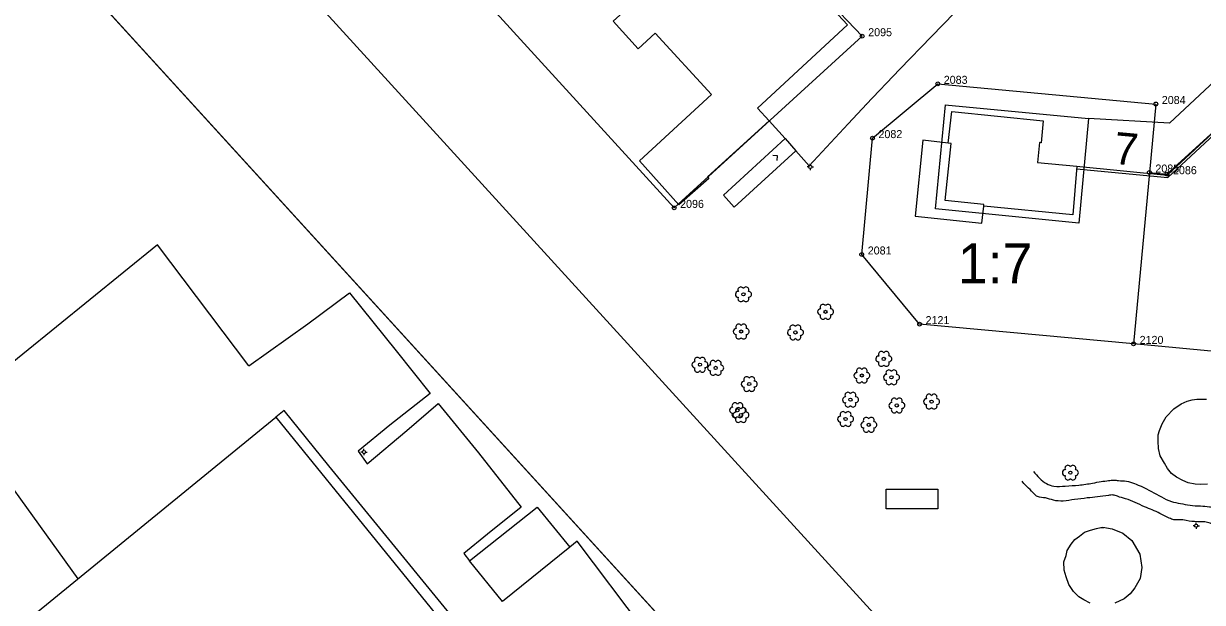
# Model space of a CAD drawing. Extents: x 1517693 to 1518189, y 6494860 to 6495280.
# Drawn here: x 1517936.6 to 1518083.9, y 6495063.4 to 6495135.7 of the extents above; entities that cross this region are included whole.
import ezdxf

# ---------------------------------------------------------------- set-up
doc = ezdxf.new("R2010")
doc.units = 0
for name, color, linetype in [('adress', 7, 'Continuous'), ('allmanbyggnad', 7, 'Continuous'), ('altan', 7, 'Continuous'), ('bostadshus', 7, 'Continuous'), ('fastighetsbeteckning', 7, 'Continuous'), ('gc_vag', 7, 'Continuous'), ('grans', 7, 'Continuous'), ('granspunkt', 7, 'Continuous'), ('granspunkt_text', 7, 'Continuous'), ('kvartersgrans', 7, 'Continuous'), ('kvartersgrans_utan_fastgr', 7, 'Continuous'), ('lovtrad', 7, 'Continuous'), ('parkeringskant', 7, 'Continuous'), ('planteringskant', 7, 'Continuous'), ('skarmtak', 7, 'Continuous'), ('staket', 7, 'Continuous'), ('stenmur', 7, 'Continuous'), ('stolpe_belysning', 7, 'Continuous'), ('trappa', 7, 'Continuous'), ('trappsymbol', 7, 'Continuous'), ('uthus', 7, 'Continuous')]:
    doc.layers.add(name, color=color, linetype=linetype)

msp = doc.modelspace()

# ---------------------------------------------------------------- linework, layer by layer
at = {"layer": 'allmanbyggnad'}
msp.add_lwpolyline([(1517931.88, 6495057.02), (1517968.08, 6495086.54), (1517994.34, 6495054.25)], dxfattribs=at)
at = {"layer": 'altan'}
msp.add_lwpolyline([(1518052.12, 6495120.78), (1518048.93, 6495121.18), (1518048, 6495111.68), (1518056.33, 6495110.79), (1518056.56, 6495112.9)], dxfattribs=at)
at = {"layer": 'bostadshus'}
for points in [[(1518010.24, 6495136.01), (1518021.49, 6495146.21), (1518024.66, 6495142.89), (1518028.99, 6495146.91), (1518039.53, 6495135.57), (1518028.29, 6495125.18), (1518029.76, 6495123.58), (1518022.02, 6495116.58), (1518022.18, 6495116.39), (1518018.47, 6495113.08), (1518013.52, 6495118.58), (1518022.53, 6495126.88), (1518015.48, 6495134.51), (1518013.35, 6495132.59), (1518010.23, 6495136.01)], [(1518052.55, 6495124.74), (1518064, 6495123.59), (1518063.75, 6495120.85), (1518063.52, 6495120.86), (1518063.29, 6495118.38), (1518068.2, 6495117.91), (1518067.7, 6495111.84), (1518056.56, 6495112.9), (1518056.56, 6495113.13), (1518051.72, 6495113.61), (1518052.47, 6495120.74), (1518052.12, 6495120.78), (1518052.55, 6495124.74)]]:
    msp.add_lwpolyline(points, dxfattribs=at)
at = {"layer": 'gc_vag'}
for points in [[(1518097.3, 6495139.7), (1518079.77, 6495123.29), (1518069.67, 6495123.88)], [(1518041.89, 6495125.55), (1518041.87, 6495125.6), (1518046.09, 6495130.04), (1518050.01, 6495134.11), (1518054.38, 6495138.58)], [(1518033.07, 6495119.83), (1518034.72, 6495117.97), (1518039.6, 6495123.22), (1518041.95, 6495125.7)]]:
    msp.add_lwpolyline(points, dxfattribs=at)
for points in [[(1518062.77, 6495079.75), (1518063.52, 6495078.94), (1518064.39, 6495078.26), (1518065.32, 6495077.95), (1518066.75, 6495077.95), (1518068.43, 6495078.07), (1518070.17, 6495078.32), (1518071.23, 6495078.51), (1518072.16, 6495078.63), (1518072.78, 6495078.69), (1518073.4, 6495078.63), (1518074.4, 6495078.57), (1518075.39, 6495078.26), (1518076.32, 6495077.89)], [(1518088.99, 6495072.13), (1518086.72, 6495072.79), (1518085.2, 6495073.19), (1518084.51, 6495073.41), (1518083.27, 6495073.5), (1518081.87, 6495073.63), (1518080.97, 6495073.75), (1518080.47, 6495073.72), (1518079.88, 6495073.88), (1518078.58, 6495074.53), (1518076.65, 6495075.37), (1518074.29, 6495076.36), (1518073.26, 6495076.67), (1518072.74, 6495076.83), (1518072.14, 6495076.77), (1518070.78, 6495076.61), (1518069.5, 6495076.46), (1518067.92, 6495076.27), (1518066.49, 6495076.08), (1518065.28, 6495076.18), (1518064.28, 6495076.46), (1518063.29, 6495076.64), (1518062.85, 6495076.98), (1518062.17, 6495077.67), (1518061.8, 6495078.01), (1518061.36, 6495078.57)], [(1518076.25, 6495077.92), (1518078.76, 6495076.61), (1518080.01, 6495076.02), (1518081.13, 6495075.77), (1518082.34, 6495075.55), (1518083.64, 6495075.46), (1518084.76, 6495075.37), (1518085.35, 6495075.28), (1518086.1, 6495075.03), (1518087.96, 6495074.44), (1518089.3, 6495074.06)]]:
    msp.add_spline(points, degree=3, dxfattribs=at)
at = {"layer": 'grans'}
for p, q in [((1518041.37, 6495134.15), (1518015.43, 6495161.24)), ((1517942.78, 6495142.01), (1518054.69, 6495019.3)), ((1517992.59, 6495140.41), (1518017.86, 6495112.7)), ((1518017.86, 6495112.7), (1518041.37, 6495134.15)), ((1518079.46, 6495116.91), (1518095.04, 6495131.13)), ((1518042.65, 6495121.42), (1518050.81, 6495128.2)), ((1518050.81, 6495128.2), (1518078.06, 6495125.68)), ((1518078.06, 6495125.68), (1518077.26, 6495117.12)), ((1518041.31, 6495106.88), (1518042.65, 6495121.42)), ((1518077.26, 6495117.12), (1518075.29, 6495095.71)), ((1518077.26, 6495117.12), (1518079.46, 6495116.91)), ((1518048.54, 6495098.18), (1518041.31, 6495106.88)), ((1518075.29, 6495095.71), (1518048.54, 6495098.18)), ((1518097.62, 6495093.65), (1518075.29, 6495095.71))]:
    msp.add_line(p, q, dxfattribs=at)
at = {"layer": 'granspunkt'}
for centre in [(1518041.37, 6495134.15), (1518050.81, 6495128.2), (1518078.06, 6495125.68), (1518042.65, 6495121.42), (1518077.26, 6495117.12), (1518079.46, 6495116.91), (1518017.86, 6495112.7), (1518041.31, 6495106.88), (1518048.54, 6495098.18), (1518075.29, 6495095.71)]:
    msp.add_circle(centre, 0.237, dxfattribs=at)
at = {"layer": 'kvartersgrans'}
msp.add_lwpolyline([(1517905.68, 6495182.68), (1517942.78, 6495142.01), (1518054.69, 6495019.3)], dxfattribs=at)
at = {"layer": 'kvartersgrans_utan_fastgr'}
msp.add_line((1517921.04, 6495195.52), (1518074.11, 6495027.69), dxfattribs=at)
at = {"layer": 'lovtrad'}
for centre in [(1518026.52, 6495101.91), (1518036.78, 6495099.72), (1518026.24, 6495097.26), (1518033.02, 6495097.14), (1518044.06, 6495093.84), (1518021.09, 6495093.11), (1518023.05, 6495092.71), (1518041.32, 6495091.76), (1518045.02, 6495091.54), (1518027.25, 6495090.7), (1518039.9, 6495088.74), (1518045.69, 6495088.02), (1518050.04, 6495088.5), (1518025.78, 6495087.42), (1518026.2, 6495086.82), (1518039.29, 6495086.33), (1518042.19, 6495085.6), (1518067.38, 6495079.63)]:
    msp.add_circle(centre, 0.2, dxfattribs=at)
for centre, start, end in [((1518026.2, 6495102.46), 29.1347, 212.3057), ((1518026.84, 6495102.46), 329.1331, 150.8613), ((1518025.89, 6495101.9), 89.5389, 268.9887), ((1518026.2, 6495101.36), 150.5831, 330.865), ((1518026.84, 6495101.36), 209.1844, 30.8583), ((1518027.16, 6495101.91), 269.1508, 90.8733), ((1518036.15, 6495099.72), 89.5389, 268.9887), ((1518036.46, 6495100.28), 29.1347, 212.3057), ((1518037.1, 6495100.28), 329.1331, 150.8613), ((1518037.42, 6495099.72), 269.1508, 90.8733), ((1518036.46, 6495099.17), 150.5831, 330.865), ((1518037.1, 6495099.17), 209.1844, 30.8583), ((1518025.61, 6495097.25), 89.5389, 268.9887), ((1518025.92, 6495097.81), 29.1347, 212.3057), ((1518025.92, 6495096.7), 150.5831, 330.865), ((1518026.56, 6495097.81), 329.1331, 150.8613), ((1518026.56, 6495096.7), 209.1844, 30.8583), ((1518026.88, 6495097.26), 269.1508, 90.8733), ((1518032.39, 6495097.14), 89.5389, 268.9887), ((1518032.7, 6495097.7), 29.1347, 212.3057), ((1518033.34, 6495097.7), 329.1331, 150.8613), ((1518033.66, 6495097.14), 269.1508, 90.8733), ((1518032.7, 6495096.59), 150.5831, 330.865), ((1518033.34, 6495096.59), 209.1844, 30.8583), ((1518020.77, 6495093.66), 29.1347, 212.3057), ((1518021.4, 6495093.66), 329.1331, 150.8613), ((1518043.43, 6495093.83), 89.5389, 268.9887), ((1518043.75, 6495094.39), 29.1347, 212.3057), ((1518044.38, 6495094.39), 329.1331, 150.8613), ((1518044.7, 6495093.84), 269.1508, 90.8733), ((1518020.45, 6495093.1), 89.5389, 268.9887), ((1518020.77, 6495092.55), 150.5831, 330.865), ((1518021.4, 6495092.55), 209.1844, 30.8583), ((1518021.72, 6495093.11), 269.1508, 90.8733), ((1518022.42, 6495092.71), 89.5389, 268.9887), ((1518022.73, 6495093.27), 29.1347, 212.3057), ((1518023.37, 6495093.27), 329.1331, 150.8613), ((1518023.69, 6495092.71), 269.1508, 90.8733), ((1518041, 6495092.31), 29.1347, 212.3057), ((1518041.64, 6495092.31), 329.1331, 150.8613), ((1518043.75, 6495093.28), 150.5831, 330.865), ((1518044.38, 6495093.28), 209.1844, 30.8583), ((1518044.7, 6495092.09), 29.1347, 212.3057), ((1518045.34, 6495092.09), 329.1331, 150.8613), ((1518022.73, 6495092.16), 150.5831, 330.865), ((1518023.37, 6495092.16), 209.1844, 30.8583), ((1518026.62, 6495090.69), 89.5389, 268.9887), ((1518026.93, 6495091.25), 29.1347, 212.3057), ((1518027.57, 6495091.25), 329.1331, 150.8613), ((1518027.89, 6495090.7), 269.1508, 90.8733), ((1518040.69, 6495091.75), 89.5389, 268.9887), ((1518041, 6495091.21), 150.5831, 330.865), ((1518041.64, 6495091.21), 209.1844, 30.8583), ((1518041.96, 6495091.76), 269.1508, 90.8733), ((1518044.39, 6495091.53), 89.5389, 268.9887), ((1518044.7, 6495090.98), 150.5831, 330.865), ((1518045.34, 6495090.98), 209.1844, 30.8583), ((1518045.66, 6495091.54), 269.1508, 90.8733), ((1518026.93, 6495090.14), 150.5831, 330.865), ((1518027.57, 6495090.14), 209.1844, 30.8583), ((1518039.58, 6495089.3), 29.1347, 212.3057), ((1518040.22, 6495089.3), 329.1331, 150.8613), ((1518025.46, 6495087.98), 29.1347, 212.3057), ((1518026.1, 6495087.98), 329.1331, 150.8613), ((1518039.27, 6495088.73), 89.5389, 268.9887), ((1518039.58, 6495088.19), 150.5831, 330.865), ((1518040.22, 6495088.19), 209.1844, 30.8583), ((1518040.54, 6495088.74), 269.1508, 90.8733), ((1518045.06, 6495088.01), 89.5389, 268.9887), ((1518045.37, 6495088.57), 29.1347, 212.3057), ((1518046.01, 6495088.57), 329.1331, 150.8613), ((1518046.33, 6495088.02), 269.1508, 90.8733), ((1518049.41, 6495088.49), 89.5389, 268.9887), ((1518049.72, 6495089.06), 29.1347, 212.3057), ((1518049.72, 6495087.95), 150.5831, 330.865), ((1518050.36, 6495089.06), 329.1331, 150.8613), ((1518050.36, 6495087.95), 209.1844, 30.8583), ((1518050.68, 6495088.5), 269.1508, 90.8733), ((1518025.15, 6495087.42), 89.5389, 268.9887), ((1518025.46, 6495086.87), 150.5831, 330.865), ((1518025.57, 6495086.81), 89.5389, 268.9887), ((1518025.88, 6495087.38), 29.1347, 212.3057), ((1518026.1, 6495086.87), 209.1844, 30.8583), ((1518026.52, 6495087.38), 329.1331, 150.8613), ((1518026.42, 6495087.42), 269.1508, 90.8733), ((1518026.84, 6495086.82), 269.1508, 90.8733), ((1518038.66, 6495086.32), 89.5389, 268.9887), ((1518038.98, 6495086.88), 29.1347, 212.3057), ((1518039.61, 6495086.88), 329.1331, 150.8613), ((1518039.93, 6495086.33), 269.1508, 90.8733), ((1518041.87, 6495086.16), 29.1347, 212.3057), ((1518042.51, 6495086.16), 329.1331, 150.8613), ((1518045.37, 6495087.47), 150.5831, 330.865), ((1518046.01, 6495087.47), 209.1844, 30.8583), ((1518025.88, 6495086.27), 150.5831, 330.865), ((1518026.52, 6495086.27), 209.1844, 30.8583), ((1518038.98, 6495085.77), 150.5831, 330.865), ((1518039.61, 6495085.77), 209.1844, 30.8583), ((1518041.56, 6495085.59), 89.5389, 268.9887), ((1518041.87, 6495085.05), 150.5831, 330.865), ((1518042.51, 6495085.05), 209.1844, 30.8583), ((1518042.83, 6495085.6), 269.1508, 90.8733), ((1518066.75, 6495079.62), 89.5389, 268.9887), ((1518067.07, 6495080.18), 29.1347, 212.3057), ((1518067.07, 6495079.07), 150.5831, 330.865), ((1518067.7, 6495080.18), 329.1331, 150.8613), ((1518067.7, 6495079.07), 209.1844, 30.8583), ((1518068.02, 6495079.63), 269.1508, 90.8733)]:
    msp.add_arc(centre, 0.366, start, end, dxfattribs=at)
at = {"layer": 'parkeringskant'}
msp.add_line((1517991.6, 6495069.53), (1517992.29, 6495068.6), dxfattribs=at)
for points in [[(1517964.72, 6495092.99), (1517953.28, 6495108.07), (1517928.01, 6495087.61), (1517943.33, 6495066.36)], [(1517964.72, 6495092.99), (1517972.07, 6495098.22), (1517977.31, 6495102.07), (1517983.13, 6495094.84), (1517987.38, 6495089.5), (1517982.34, 6495085.57), (1517978.37, 6495082.32), (1517979.49, 6495080.73), (1517984.46, 6495084.9), (1517988.37, 6495088.28), (1517993.4, 6495082.12), (1517998.74, 6495075.31), (1517994.53, 6495071.92), (1517991.6, 6495069.53)], [(1517994.73, 6495054.69), (1517995.32, 6495055.28), (1517988.37, 6495063.76), (1517982.21, 6495071.32), (1517974.72, 6495080.46), (1517969.13, 6495087.4), (1517968.08, 6495086.54)], [(1518003.87, 6495051.87), (1518014.03, 6495060.08), (1518005.76, 6495071.07), (1518004.81, 6495070.32)]]:
    msp.add_lwpolyline(points, dxfattribs=at)
at = {"layer": 'planteringskant'}
for points in [[(1518084.54, 6495078.18), (1518083.69, 6495078.15), (1518082.97, 6495078.18), (1518082.09, 6495078.36), (1518081.43, 6495078.63), (1518080.64, 6495079.08), (1518080.01, 6495079.51), (1518079.53, 6495080.14), (1518079.14, 6495080.83), (1518078.59, 6495081.74), (1518078.41, 6495082.65), (1518078.35, 6495083.55), (1518078.35, 6495084.34), (1518078.53, 6495084.91), (1518078.86, 6495085.73), (1518079.35, 6495086.6), (1518080.31, 6495087.6), (1518081.25, 6495088.23), (1518082, 6495088.56), (1518082.61, 6495088.71), (1518083.18, 6495088.81), (1518083.18, 6495088.81)], [(1518083.21, 6495088.81), (1518084.39, 6495088.81)], [(1518069.86, 6495063.32), (1518069.07, 6495063.74), (1518068.44, 6495064.11), (1518067.77, 6495064.77), (1518067.2, 6495065.65), (1518066.84, 6495066.61), (1518066.6, 6495067.46), (1518066.57, 6495068.48), (1518066.84, 6495069.27), (1518066.99, 6495069.9), (1518067.5, 6495070.69), (1518067.95, 6495071.29), (1518068.53, 6495071.71), (1518069.13, 6495072.17), (1518069.89, 6495072.44), (1518070.64, 6495072.65), (1518071.21, 6495072.77), (1518071.55, 6495072.77)], [(1518071.45, 6495072.8), (1518072.6, 6495072.62), (1518073.96, 6495072.08), (1518075.05, 6495071.14), (1518076.07, 6495069.45), (1518076.31, 6495067.76), (1518076.1, 6495066.4), (1518075.44, 6495065.22), (1518074.86, 6495064.47), (1518074.11, 6495063.87), (1518072.93, 6495063.32)]]:
    msp.add_lwpolyline(points, dxfattribs=at)
at = {"layer": 'skarmtak'}
msp.add_lwpolyline([(1518051.75, 6495125.58), (1518069.67, 6495123.88), (1518068.46, 6495110.79), (1518050.53, 6495112.59), (1518051.78, 6495125.58)], dxfattribs=at)
at = {"layer": 'staket'}
msp.add_line((1518029.76, 6495123.58), (1518031.76, 6495121.35), dxfattribs=at)
at = {"layer": 'stenmur'}
for points in [[(1518068.15, 6495117.91), (1518079.47, 6495116.8), (1518086.88, 6495123.66)], [(1518068.17, 6495117.6), (1518079.57, 6495116.49), (1518087.08, 6495123.44)]]:
    msp.add_lwpolyline(points, dxfattribs=at)
msp.add_lwpolyline([(1518044.36, 6495077.55), (1518050.8, 6495077.55), (1518050.8, 6495075.09), (1518044.36, 6495075.09)], close=True, dxfattribs=at)
at = {"layer": 'stolpe_belysning'}
for p, q in [((1518034.67, 6495117.82), (1518034.47, 6495117.82)), ((1518034.87, 6495118.02), (1518034.87, 6495118.22)), ((1518034.87, 6495117.62), (1518034.87, 6495117.42)), ((1518035.07, 6495117.82), (1518035.27, 6495117.82)), ((1517978.9, 6495082.19), (1517978.7, 6495082.19)), ((1517979.1, 6495082.39), (1517979.1, 6495082.59)), ((1517979.3, 6495082.19), (1517979.5, 6495082.19)), ((1517979.1, 6495081.99), (1517979.1, 6495081.79)), ((1518083.11, 6495073.2), (1518083.11, 6495073.4)), ((1518082.91, 6495073), (1518082.71, 6495073)), ((1518083.11, 6495072.8), (1518083.11, 6495072.6)), ((1518083.31, 6495073), (1518083.51, 6495073))]:
    msp.add_line(p, q, dxfattribs=at)
for centre in [(1518034.87, 6495117.82), (1517979.1, 6495082.19), (1518083.11, 6495073)]:
    msp.add_circle(centre, 0.2, dxfattribs=at)
at = {"layer": 'trappa'}
msp.add_lwpolyline([(1518031.76, 6495121.35), (1518033.09, 6495119.84), (1518025.37, 6495112.78), (1518024.04, 6495114.29), (1518031.76, 6495121.35)], dxfattribs=at)
at = {"layer": 'trappsymbol'}
msp.add_lwpolyline([(1518030.76, 6495118.61), (1518030.8, 6495119.21), (1518030.2, 6495119.25)], dxfattribs=at)
at = {"layer": 'uthus'}
msp.add_lwpolyline([(1517992.29, 6495068.6), (1518000.76, 6495075.3), (1518004.81, 6495070.32), (1517996.42, 6495063.51), (1517992.27, 6495068.63)], dxfattribs=at)

# ---------------------------------------------------------------- texts
at = {"layer": 'adress'}
msp.add_text('7', height=4, rotation=354.8003, dxfattribs=at).set_placement((1518072.7, 6495118.22))
at = {"layer": 'fastighetsbeteckning'}
msp.add_text('1:7', height=5, rotation=0.0021, dxfattribs=at).set_placement((1518053.33, 6495103.28))
at = {"layer": 'granspunkt_text'}
for s, p in [('2095', (1518042.12, 6495134.15)), ('2083', (1518051.56, 6495128.2)), ('2084', (1518078.81, 6495125.68)), ('2082', (1518043.4, 6495121.42)), ('2085', (1518078.01, 6495117.12)), ('2086', (1518080.21, 6495116.91)), ('2096', (1518018.61, 6495112.7)), ('2081', (1518042.06, 6495106.88)), ('2121', (1518049.29, 6495098.18)), ('2120', (1518076.04, 6495095.71))]:
    msp.add_text(s, height=1, dxfattribs=at).set_placement(p)

doc.saveas('drawing.dxf')
